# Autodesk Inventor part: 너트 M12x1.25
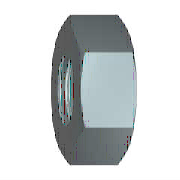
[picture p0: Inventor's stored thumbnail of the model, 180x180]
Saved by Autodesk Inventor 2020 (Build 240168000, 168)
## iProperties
Created: 2012-02
Part Number: 너트 M12x1.25
Material: 강철, 연강
Description: 6각 너트
Document SubType Name: Modeling
Standard: KS B 1012
Designer: mduedu
Standards Organization: KS
Language: ko-KR
Size Designation: M12x1.25
Categories: <MemberInstance><Categories><Category DisplayName="조임쇠" InternalName="e4da775c-781d-43d5-af7c-5136215cf5a6" Mnemonic="FSTN"><Category DisplayName="너트" InternalN
Density: 1 g/cm^3
Appearance: 강철
IsCustomPart: 1
Author: mduedu
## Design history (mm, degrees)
sketch "스케치1"
  geometry: L1 (-10.97, 0)-(-5.485, 9.5); L2 (-5.485, 9.5)-(5.485, 9.5); L3 (5.485, 9.5)-(10.97, 0); L4 (10.97, 0)-(5.485, -9.5); L5 (5.485, -9.5)-(-5.485, -9.5); L6 (-5.485, -9.5)-(-10.97, 0); 2 further points
  constraints: 12 end point, 1 coincident, 1 horizontal, 11 other
  dimensions: "d0" = 21.93931 distance of L3.end L1.start (= 1.1547 x SW)
extrude "본체" new body sketch "스케치1" distance "d1" = 10 (= KOH); taper "d2" = 0 deg
sketch "스케치2"
  geometry: L1 (0, 5.485)-(0, 10.97) reference; L2 (0, 10.97)-(10, 10.97) reference; L3 (10, 5.485)-(10, 10.97) reference; L4 (-2, 0)-(12, 0) reference; L5 (0.849, 10.97)-(0, 9.5); L6 (9.151, 10.97)-(10, 9.5)
  constraints: 4 end point, 4 point on line
  dimensions: "d3" = 30 deg angle of L1 L5 (= ANG1); "d4" = 30 deg angle of L3 L6 (= ANG2); "d5" = 19 diameter of L5.end L4 (= SW0); "d6" = 19 diameter of L6.end L4 (= SW01)
revolve "모따기1" sketch "스케치2" stored, may be unused: angle "d7" = 90 deg
sketch "스케치3"
  geometry: A1 r 9.5 centre (0, 0) between (-4.75, -8.227) and (4.75, -8.227) reference; 1 further point
  constraints: 1 coincident
hole "스레드" sketch "스케치3" at (0, 0) diameter "d25" = 10.647; stored, may be unused: countersink angle "d29" = 82 deg, drill point angle "d31" = 118 deg; dims "d26" = 6, "d27" = 4, "d28" = 2, "d30" = 8
workaxis "Work Axis1"
workplane "Work Plane1"
body "Solid1"
chamfer "모따기2" distance "d8" = 0.67658 (= -0.5 x GD1 + 0.5 x NND); stored, may be unused: angle "d9" = 30 deg, second distance "d40" = 0.67658 (= -0.5 x GD1 + 0.5 x NND)
chamfer "모따기3" distance "d10" = 0.67658 (= -0.5 x GD1 + 0.5 x NND); stored, may be unused: angle "d11" = 30 deg, second distance "d41" = 0.67658 (= -0.5 x GD1 + 0.5 x NND)
other parameters: "ANG1" = 30 deg [user parameter; used in 1 equation term], "ANG2" = 30 deg [user parameter; used in 1 equation term], "NND" = 12 [user parameter; used in 4 equation terms], "KOH" = 10 [user parameter; used in 1 equation term], "SW" = 19 [user parameter; used in 4 equation terms], "SW0" = 19 (= SW) [user parameter; used in 1 equation term], "SW01" = 19 (= SW) [user parameter; used in 1 equation term], "GD1" = 10.64684 (computed from THREADDIA, PTC, TOA) [user parameter; used in 4 equation terms], "d13" = 0, "d14" = 0, "d39" = 0, "d42" = 0, "GUL" = 0.67658 (= 0.541266 x PTC) [user parameter], "TPU" = 8 (computed from PTC) [user parameter], "THREADDIA" = 12 [user parameter; used in 1 equation term], "TOA" = 30 deg [user parameter; used in 1 equation term], "PTC" = 1.25 [user parameter; used in 4 equation terms], "E0" = 21.945 (= 1.155 x SW) [user parameter], "GAL" = 0.67658 (= 0.541266 x PTC) [user parameter]
